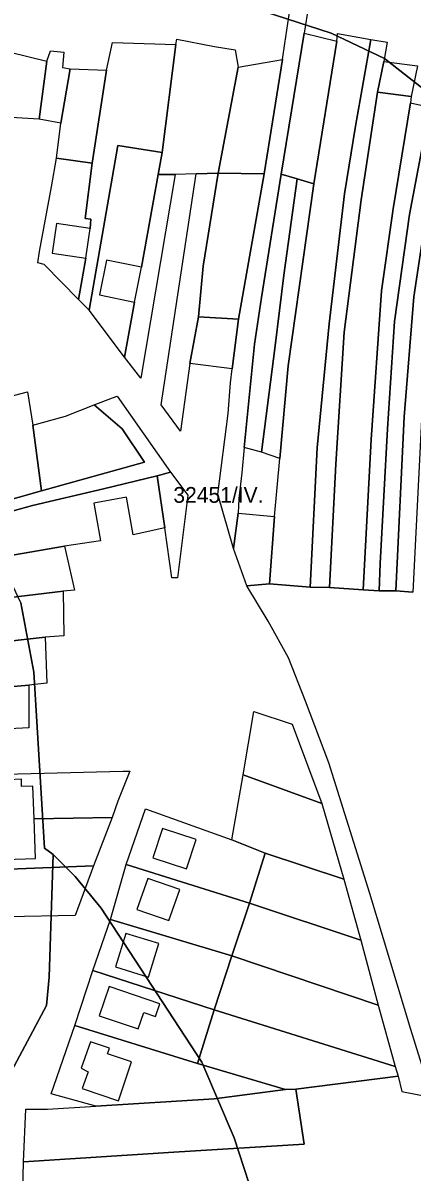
# Model space of a CAD drawing. Extents: x -532083 to -529270, y -1180561 to -1176456.
# Drawn here: x -530525.7 to -530402.1, y -1178712.9 to -1178347.7 of the extents above; entities that cross this region are included whole.
import ezdxf

# ---------------------------------------------------------------- set-up
doc = ezdxf.new("R2010")
doc.units = 0
for name, color, linetype in [('95560013', 7, 'Continuous'), ('95590013', 7, 'Continuous'), ('95610013', 7, 'Continuous'), ('95660013', 7, 'Continuous')]:
    doc.layers.add(name, color=color, linetype=linetype)

msp = doc.modelspace()

# ---------------------------------------------------------------- linework, layer by layer
at = {"layer": '95560013'}
for points in [[(-530522.6463, -1178501.05645), (-530547.9363, -1178508.08045), (-530571.6693, -1178500.40545), (-530569.5943, -1178495.85245), (-530562.2023, -1178491.29945), (-530545.9913, -1178503.52745), (-530541.1923, -1178502.48745), (-530519.7933, -1178496.37245), (-530487.1113, -1178487.26645), (-530494.1143, -1178476.72945), (-530503.0633, -1178469.05345), (-530497.2273, -1178466.84245), (-530495.8003, -1178466.32245), (-530478.8143, -1178490.47645), (-530483.0043, -1178491.58245), (-530500.0803, -1178495.72245)], [(-530512.5313, -1178513.93545), (-530533.9293, -1178517.70745), (-530557.7933, -1178522.39045), (-530556.8853, -1178520.95945), (-530552.4753, -1178511.98345), (-530550.5303, -1178508.86145), (-530547.9363, -1178508.08045), (-530522.6463, -1178501.05645), (-530500.0803, -1178495.72245), (-530483.0043, -1178491.58245), (-530480.5783, -1178508.17345), (-530490.6393, -1178510.38245), (-530492.8343, -1178498.41145), (-530503.1953, -1178500.31145), (-530500.9993, -1178512.28245)], [(-530523.8323, -1178558.21045), (-530581.3273, -1178563.22545), (-530579.5923, -1178559.45445), (-530573.6663, -1178549.01545), (-530518.5893, -1178542.92445), (-530518.0973, -1178557.55245)], [(-530534.2023, -1178572.21545), (-530588.4103, -1178576.41945), (-530581.3273, -1178563.22545), (-530523.8323, -1178558.21045), (-530523.8323, -1178571.68745)], [(-530430.7143, -1178595.81645), (-530455.6913, -1178586.70645), (-530452.3453, -1178566.53245), (-530440.1643, -1178570.53545)], [(-530453.7723, -1178627.43145), (-530492.8773, -1178615.19845), (-530486.7863, -1178597.50145), (-530459.3363, -1178607.29945), (-530448.7843, -1178611.53445)], [(-530484.4563, -1178613.04545), (-530473.7753, -1178616.57145), (-530470.6933, -1178607.23645), (-530481.3743, -1178603.71045)], [(-530418.3593, -1178639.20545), (-530453.7723, -1178627.43145), (-530448.7843, -1178611.53445), (-530423.7843, -1178619.83245)], [(-530541.6603, -1178631.98745), (-530549.2313, -1178632.22145), (-530543.5383, -1178617.16645), (-530503.2233, -1178615.53345), (-530509.0763, -1178631.34045), (-530530.6133, -1178631.76145), (-530530.8623, -1178619.63145), (-530541.9083, -1178619.85745)], [(-530459.3363, -1178644.17645), (-530497.9173, -1178632.68345), (-530492.8773, -1178615.19845), (-530453.7723, -1178627.43145)], [(-530479.3193, -1178632.98345), (-530475.8793, -1178623.09345), (-530486.0203, -1178619.56745), (-530489.4593, -1178629.45645)], [(-530412.8823, -1178659.85445), (-530459.3363, -1178644.17645), (-530453.7723, -1178627.43145), (-530418.3593, -1178639.20545)], [(-530464.9003, -1178661.30545), (-530503.4643, -1178648.79545), (-530497.9173, -1178632.68345), (-530459.3363, -1178644.17645)], [(-530496.2743, -1178647.70845), (-530485.8473, -1178650.94645), (-530482.5383, -1178640.28645), (-530492.9643, -1178637.04945)], [(-530407.4063, -1178679.36645), (-530464.9003, -1178661.30545), (-530459.3363, -1178644.17645), (-530412.8823, -1178659.85445)], [(-530470.2723, -1178678.43545), (-530509.2203, -1178666.31045), (-530503.4643, -1178648.79545), (-530464.9003, -1178661.30545)], [(-530489.0963, -1178667.41845), (-530487.3033, -1178662.17845), (-530483.6243, -1178663.43645), (-530482.2483, -1178659.41345), (-530498.2603, -1178653.93445), (-530501.4303, -1178663.19745)], [(-530442.2613, -1178686.71145), (-530470.2723, -1178678.43545), (-530464.9003, -1178661.30545), (-530407.4063, -1178679.36645), (-530406.4623, -1178682.39745), (-530438.9993, -1178686.51945)], [(-530464.9003, -1178689.59845), (-530502.5053, -1178691.90845), (-530516.7033, -1178688.05845), (-530509.2203, -1178666.31045), (-530470.2723, -1178678.43545), (-530442.2613, -1178686.71145)], [(-530491.1623, -1178677.89945), (-530498.7793, -1178675.29245), (-530498.1363, -1178673.48445), (-530504.2183, -1178671.49245), (-530507.1973, -1178679.83445), (-530505.0153, -1178681.02245), (-530506.8253, -1178686.31045), (-530495.3823, -1178690.22745)], [(-530436.3133, -1178704.03345), (-530477.7553, -1178706.53545), (-530525.5283, -1178709.61545), (-530524.7613, -1178692.87045), (-530517.8543, -1178692.87045), (-530502.5053, -1178691.90845), (-530464.9003, -1178689.59845), (-530442.2613, -1178686.71145), (-530438.9993, -1178686.51945)]]:
    msp.add_lwpolyline(points, close=True, dxfattribs=at)
for points in [[(-530397.4543, -1178683.63745), (-530402.4883, -1178667.57045), (-530415.5303, -1178624.41745), (-530428.5733, -1178582.87245), (-530435.9723, -1178563.29245), (-530441.3173, -1178549.48245), (-530447.7953, -1178537.78545), (-530454.5963, -1178526.57545), (-530447.3503, -1178525.93345), (-530434.4043, -1178526.98645), (-530428.2803, -1178527.16145), (-530417.6083, -1178527.86345), (-530412.5343, -1178528.21445), (-530407.2863, -1178528.21445), (-530401.8623, -1178528.56545)], [(-530690.5463, -1179014.35945), (-530643.5763, -1178951.29245), (-530584.3203, -1178873.36445), (-530554.0423, -1178832.09445), (-530548.8193, -1178816.37645), (-530540.7243, -1178780.48645), (-530532.1063, -1178757.95845), (-530525.8393, -1178723.11645), (-530525.5283, -1178709.61545), (-530477.7553, -1178706.53545), (-530436.3133, -1178704.03345), (-530438.9993, -1178686.51945), (-530406.4623, -1178682.39745), (-530405.3293, -1178687.32245), (-530368.5043, -1178694.52145), (-530341.5003, -1178699.06845), (-530299.9553, -1178705.13045), (-530306.2123, -1178774.10145), (-530309.2763, -1178821.52745), (-530306.6503, -1178835.14045), (-530310.5893, -1178859.73145), (-530321.3073, -1178925.52945), (-530332.4003, -1178981.99545)]]:
    msp.add_lwpolyline(points, dxfattribs=at)
at = {"layer": '95590013'}
for points in [[(-530457.1803, -1178441.84045), (-530449.0443, -1178395.65845), (-530443.2013, -1178359.27145), (-530442.5303, -1178354.22245), (-530440.5683, -1178341.56245), (-530434.9903, -1178342.27945), (-530436.3673, -1178350.94645), (-530443.6303, -1178395.78845), (-530449.9563, -1178434.90545), (-530452.1273, -1178449.81345), (-530455.4673, -1178482.64545), (-530456.1793, -1178490.62945), (-530457.0653, -1178498.85445), (-530457.3553, -1178503.46445), (-530458.8073, -1178514.71645), (-530463.8283, -1178497.49545), (-530460.5003, -1178471.84445), (-530459.7253, -1178462.06245), (-530459.2133, -1178457.60445)], [(-530505.9623, -1178409.85745), (-530503.6913, -1178392.31645), (-530499.1493, -1178362.70245), (-530497.2263, -1178353.88645), (-530477.0923, -1178354.55945), (-530481.4553, -1178388.89145), (-530495.5153, -1178386.62145), (-530504.5993, -1178439.01645), (-530508.0063, -1178435.59945), (-530505.6773, -1178422.43445), (-530504.3033, -1178413.04345), (-530504.1453, -1178410.08545)], [(-530477.3343, -1178395.84345), (-530482.6963, -1178395.84345), (-530481.4553, -1178388.89145), (-530477.0923, -1178354.55945), (-530476.7573, -1178352.87645), (-530464.8443, -1178355.20745), (-530458.2773, -1178356.26645), (-530457.2943, -1178361.79545), (-530463.6513, -1178395.47245), (-530470.6773, -1178395.65845)], [(-530441.4403, -1178456.68145), (-530433.2363, -1178398.80345), (-530425.9743, -1178353.45845), (-530425.7233, -1178351.07145), (-530415.2043, -1178352.95645), (-530420.0153, -1178380.46745), (-530423.5873, -1178401.96645), (-530428.4113, -1178443.31045), (-530432.2193, -1178482.69445), (-530434.4043, -1178526.98645), (-530447.3503, -1178525.93345), (-530445.7813, -1178504.56945), (-530444.1123, -1178486.16245)], [(-530443.6303, -1178395.78845), (-530436.3673, -1178350.94645), (-530425.9743, -1178353.45845), (-530433.2363, -1178398.80345), (-530438.6213, -1178397.29545)], [(-530423.5873, -1178401.96645), (-530420.0153, -1178380.46745), (-530415.2043, -1178352.95645), (-530409.9453, -1178353.83545), (-530411.0843, -1178359.96345), (-530413.0693, -1178369.71745), (-530418.2293, -1178403.95745), (-530423.6523, -1178445.93545), (-530426.2693, -1178487.94545), (-530428.2803, -1178527.16145), (-530434.4043, -1178526.98645), (-530432.2193, -1178482.69445), (-530428.4113, -1178443.31045)], [(-530520.5053, -1178378.26645), (-530533.1183, -1178377.56345), (-530529.7583, -1178356.97945), (-530518.0533, -1178359.81645)], [(-530513.6843, -1178379.55945), (-530520.5053, -1178378.26645), (-530518.0533, -1178359.81645), (-530516.9573, -1178356.60645), (-530512.6733, -1178356.94545), (-530513.1343, -1178361.90245), (-530510.7313, -1178362.24645)], [(-530463.6513, -1178395.47245), (-530457.2943, -1178361.79545), (-530443.2013, -1178359.27145), (-530449.0443, -1178395.65845)], [(-530402.3523, -1178371.11145), (-530413.0693, -1178369.71745), (-530411.0843, -1178359.96345), (-530400.3683, -1178361.35645)], [(-530503.6913, -1178392.31645), (-530515.0463, -1178390.72245), (-530513.6843, -1178379.55945), (-530510.7313, -1178362.24645), (-530499.1493, -1178362.70245)], [(-530418.2293, -1178403.95745), (-530413.0693, -1178369.71745), (-530402.3523, -1178371.11145), (-530402.5513, -1178373.10145), (-530408.1073, -1178406.74445), (-530411.7543, -1178432.80745), (-530415.0853, -1178480.06845), (-530417.6083, -1178527.86345), (-530428.2803, -1178527.16145), (-530426.2693, -1178487.94545), (-530423.6523, -1178445.93545)], [(-530408.1073, -1178406.74445), (-530402.5513, -1178373.10145), (-530396.3983, -1178374.49545), (-530402.9473, -1178408.53545), (-530407.7093, -1178442.59345), (-530409.8503, -1178476.72745), (-530412.2303, -1178519.45345), (-530412.5343, -1178528.21445), (-530417.6083, -1178527.86345), (-530415.0853, -1178480.06845), (-530411.7543, -1178432.80745)], [(-530402.9473, -1178408.53545), (-530396.3983, -1178374.49545), (-530390.8423, -1178375.29145), (-530397.7883, -1178410.12845), (-530401.5223, -1178434.71745), (-530404.6153, -1178472.90845), (-530407.2863, -1178528.21445), (-530412.5343, -1178528.21445), (-530412.2303, -1178519.45345), (-530409.8503, -1178476.72745), (-530407.7093, -1178442.59345)], [(-530397.7883, -1178410.12845), (-530390.8423, -1178375.29145), (-530385.4833, -1178376.28645), (-530386.8723, -1178382.85645), (-530392.4293, -1178411.52145), (-530396.2863, -1178436.38745), (-530399.1423, -1178473.86245), (-530401.8623, -1178528.56545), (-530407.2863, -1178528.21445), (-530404.6153, -1178472.90845), (-530401.5223, -1178434.71745)], [(-530504.5993, -1178439.01645), (-530495.5153, -1178386.62145), (-530481.4553, -1178388.89145), (-530482.6963, -1178395.84345), (-530487.9833, -1178425.36345), (-530499.0943, -1178423.11445), (-530501.3273, -1178434.14245), (-530490.2173, -1178436.39245), (-530493.4203, -1178453.89545)], [(-530520.9513, -1178423.98145), (-530520.3753, -1178420.33045), (-530516.6023, -1178399.83045), (-530515.0463, -1178390.72245), (-530503.6913, -1178392.31645), (-530505.9623, -1178409.85745), (-530504.1453, -1178410.08545), (-530504.3033, -1178413.04345), (-530515.0323, -1178411.47345), (-530516.4063, -1178420.86445), (-530505.6773, -1178422.43445), (-530508.0063, -1178435.59945), (-530518.9073, -1178424.43745)], [(-530487.9833, -1178425.36345), (-530482.6963, -1178395.84345), (-530477.3343, -1178395.84345), (-530488.2433, -1178460.57245), (-530493.4203, -1178453.89545), (-530490.2173, -1178436.39245)], [(-530481.7713, -1178469.10345), (-530470.6773, -1178395.65845), (-530463.6513, -1178395.47245), (-530468.4583, -1178424.96245), (-530469.9383, -1178441.09845), (-530472.7113, -1178455.93545), (-530475.6703, -1178477.44945)], [(-530469.9383, -1178441.09845), (-530468.4583, -1178424.96245), (-530463.6513, -1178395.47245), (-530449.0443, -1178395.65845), (-530457.1803, -1178441.84045)], [(-530449.9563, -1178434.90545), (-530443.6303, -1178395.78845), (-530438.6213, -1178397.29545), (-530442.7763, -1178427.87045), (-530445.6153, -1178450.31645), (-530449.9563, -1178484.15245), (-530455.4673, -1178482.64545), (-530452.1273, -1178449.81345)], [(-530442.7763, -1178427.87045), (-530438.6213, -1178397.29545), (-530433.2363, -1178398.80345), (-530441.4403, -1178456.68145), (-530444.1123, -1178486.16245), (-530449.9563, -1178484.15245), (-530445.6153, -1178450.31645)], [(-530459.2133, -1178457.60445), (-530472.7113, -1178455.93545), (-530469.9383, -1178441.09845), (-530457.1803, -1178441.84045)], [(-530541.1923, -1178502.48745), (-530546.1033, -1178470.29945), (-530536.8323, -1178468.23245), (-530524.2423, -1178464.90345), (-530522.5173, -1178475.55845), (-530519.7933, -1178496.37245)], [(-530519.7933, -1178496.37245), (-530522.5173, -1178475.55845), (-530512.1413, -1178472.69645), (-530503.0633, -1178469.05345), (-530494.1143, -1178476.72945), (-530487.1113, -1178487.26645)], [(-530454.5963, -1178526.57545), (-530458.8073, -1178514.71645), (-530457.3553, -1178503.46445), (-530445.7813, -1178504.56945), (-530447.3503, -1178525.93345)], [(-530512.8543, -1178528.29645), (-530564.8483, -1178534.51545), (-530561.8133, -1178529.93645), (-530557.7933, -1178522.39045), (-530533.9293, -1178517.70745), (-530512.5313, -1178513.93545), (-530509.2883, -1178527.98445)], [(-530518.5893, -1178542.92445), (-530573.6663, -1178549.01545), (-530564.8483, -1178534.51545), (-530512.8543, -1178528.29645), (-530512.6903, -1178542.43145)], [(-530531.7413, -1178601.00845), (-530537.0943, -1178601.21445), (-530531.4563, -1178586.42545), (-530493.9933, -1178585.49945), (-530491.7423, -1178585.49945), (-530495.5693, -1178594.98345), (-530497.3703, -1178600.17745), (-530522.1603, -1178600.66945), (-530522.5303, -1178590.21645), (-530526.1023, -1178590.34345), (-530526.1663, -1178588.02745), (-530530.2803, -1178588.20745), (-530530.2873, -1178590.49145), (-530532.1113, -1178590.55545)], [(-530448.7843, -1178611.53445), (-530459.3363, -1178607.29945), (-530455.6913, -1178586.70645), (-530430.7143, -1178595.81645), (-530423.7843, -1178619.83245)], [(-530503.2233, -1178615.53345), (-530543.5383, -1178617.16645), (-530537.0943, -1178601.21445), (-530531.7413, -1178601.00845), (-530531.2963, -1178613.55545), (-530521.7163, -1178613.21645), (-530522.1603, -1178600.66945), (-530497.3703, -1178600.17745)]]:
    msp.add_lwpolyline(points, close=True, dxfattribs=at)
at = {"layer": '95610013'}
msp.add_lwpolyline([(-530480.5783, -1178508.17345), (-530483.0043, -1178491.58245), (-530478.8143, -1178490.47645), (-530473.3013, -1178497.77645), (-530476.6093, -1178524.10145), (-530478.3733, -1178524.10145)], close=True, dxfattribs=at)
at = {"layer": '95660013'}
for points in [[(-530443.8753, -1178999.00045), (-530428.1873, -1178967.00045), (-530412.8753, -1178944.00045), (-530390.1253, -1178908.00045), (-530379.3753, -1178882.00045), (-530371.0003, -1178848.00045), (-530370.1253, -1178829.00045), (-530370.6253, -1178802.00045), (-530375.6253, -1178737.00045), (-530379.3753, -1178654.00045), (-530382.8753, -1178592.00045), (-530380.8123, -1178566.00045), (-530374.8123, -1178526.00045), (-530374.8123, -1178490.00045), (-530378.6253, -1178463.00045), (-530384.6253, -1178443.00045), (-530383.6873, -1178430.00045), (-530380.3123, -1178401.00045), (-530383.6873, -1178388.00045), (-530387.8753, -1178377.00045), (-530410.8123, -1178359.00045), (-530427.8123, -1178351.00045), (-530452.3753, -1178343.00045)], [(-530452.3753, -1178343.00045), (-530427.8123, -1178351.00045), (-530410.8123, -1178359.00045), (-530387.8753, -1178377.00045), (-530383.6873, -1178388.00045), (-530380.3123, -1178401.00045), (-530383.6873, -1178430.00045), (-530384.6253, -1178443.00045), (-530378.6253, -1178463.00045), (-530374.8123, -1178490.00045), (-530374.8123, -1178526.00045), (-530380.8123, -1178566.00045), (-530382.8753, -1178592.00045), (-530379.3753, -1178654.00045), (-530375.6253, -1178737.00045), (-530370.6253, -1178802.00045), (-530370.1253, -1178829.00045), (-530371.0003, -1178848.00045), (-530379.3753, -1178882.00045), (-530390.1253, -1178908.00045), (-530412.8753, -1178944.00045), (-530428.1873, -1178967.00045), (-530443.8753, -1178999.00045)], [(-530482.3753, -1179007.00045), (-530459.3753, -1178970.00045), (-530450.0003, -1178942.00045), (-530444.3123, -1178914.00045), (-530439.3753, -1178865.00045), (-530435.6873, -1178792.00045), (-530441.3753, -1178755.00045), (-530458.6253, -1178702.00045), (-530468.8753, -1178678.00045), (-530500.8753, -1178629.00045), (-530509.1253, -1178619.00045), (-530516.1253, -1178612.00045), (-530518.8753, -1178610.00045), (-530522.1873, -1178554.00045), (-530526.3123, -1178532.00045), (-530535.3123, -1178513.00045), (-530549.6253, -1178494.00045), (-530568.5003, -1178476.00045), (-530580.8123, -1178470.00045), (-530569.3753, -1178446.00045), (-530557.8753, -1178419.00045), (-530548.1253, -1178386.00045), (-530536.6873, -1178345.00045)], [(-530526.3123, -1178532.00045), (-530522.1873, -1178554.00045), (-530518.8753, -1178610.00045), (-530516.1253, -1178612.00045), (-530517.3753, -1178651.00045), (-530518.1873, -1178660.00045), (-530533.8123, -1178689.00045)], [(-530680.6253, -1178987.00045), (-530659.1873, -1178976.00045), (-530623.1253, -1178960.00045), (-530580.1253, -1178909.00045), (-530563.6873, -1178878.00045), (-530559.6253, -1178861.00045), (-530549.8123, -1178813.00045), (-530541.6253, -1178742.00045), (-530537.3753, -1178699.00045), (-530533.8123, -1178689.00045), (-530518.1873, -1178660.00045), (-530517.3753, -1178651.00045), (-530516.1253, -1178612.00045), (-530509.1253, -1178619.00045), (-530500.8753, -1178629.00045), (-530468.8753, -1178678.00045), (-530458.6253, -1178702.00045), (-530441.3753, -1178755.00045), (-530435.6873, -1178792.00045), (-530439.3753, -1178865.00045), (-530444.3123, -1178914.00045), (-530450.0003, -1178942.00045), (-530459.3753, -1178970.00045), (-530482.3753, -1179007.00045)]]:
    msp.add_lwpolyline(points, dxfattribs=at)

# ---------------------------------------------------------------- texts
msp.add_text('32451/IV.', height=5, rotation=0, dxfattribs=at).set_placement((-530477.9033, -1178500.19173))

doc.saveas('drawing.dxf')
